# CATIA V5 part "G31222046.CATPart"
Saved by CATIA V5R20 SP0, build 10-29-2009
Part number: G31222046
Revision: 5
Definition: design
Nomenclature: G31222046
Source: made
Description: NOT SPECIFIED
Bounding box of the stored display mesh (mm): x -8 to 46, y -17.322 to 17.322, z -17.5 to 17.5
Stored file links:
  C:\Users\Raffaele\Desktop\3D X SITO CF\BOLEX\23-BUSH REF 312\G31222046.CATPart

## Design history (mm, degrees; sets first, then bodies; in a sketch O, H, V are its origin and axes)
Body1 "MANIFOLD_SOLID_BREP #10463" (main body)
  Solid1: solid without history
Body2 "MANIFOLD_SOLID_BREP #10614"
  Solid2: solid without history
Body3 "MANIFOLD_SOLID_BREP #10765"
  Solid3: solid without history
Body4 "MANIFOLD_SOLID_BREP #10916"
  Solid4: solid without history
Body5 "MANIFOLD_SOLID_BREP #11067"
  Solid5: solid without history
Body6 "MANIFOLD_SOLID_BREP #11216"
  Solid6: solid without history
Body7 "MANIFOLD_SOLID_BREP #11365"
  Solid7: solid without history
Body8 "MANIFOLD_SOLID_BREP #11514"
  Solid8: solid without history
Body9 "MANIFOLD_SOLID_BREP #11663"
  Solid9: solid without history
Body10 "MANIFOLD_SOLID_BREP #11812"
  Solid10: solid without history
Body11 "MANIFOLD_SOLID_BREP #11961"
  Solid11: solid without history
Body12 "MANIFOLD_SOLID_BREP #12110"
  Solid12: solid without history
Body13 "MANIFOLD_SOLID_BREP #12259"
  Solid13: solid without history
Body14 "MANIFOLD_SOLID_BREP #12408"
  Solid14: solid without history
Body15 "MANIFOLD_SOLID_BREP #12557"
  Solid15: solid without history
Body16 "MANIFOLD_SOLID_BREP #12706"
  Solid16: solid without history
Body17 "MANIFOLD_SOLID_BREP #12855"
  Solid17: solid without history
Body18 "MANIFOLD_SOLID_BREP #13004"
  Solid18: solid without history
Body19 "MANIFOLD_SOLID_BREP #13153"
  Solid19: solid without history
Body20 "MANIFOLD_SOLID_BREP #13302"
  Solid20: solid without history
Body21 "MANIFOLD_SOLID_BREP #13451"
  Solid21: solid without history
Body22 "MANIFOLD_SOLID_BREP #13600"
  Solid22: solid without history
Body23 "MANIFOLD_SOLID_BREP #13749"
  Solid23: solid without history
Body24 "MANIFOLD_SOLID_BREP #13898"
  Solid24: solid without history
Body25 "MANIFOLD_SOLID_BREP #14047"
  Solid25: solid without history
Body26 "MANIFOLD_SOLID_BREP #14196"
  Solid26: solid without history
Body27 "MANIFOLD_SOLID_BREP #14345"
  Solid27: solid without history
Body28 "MANIFOLD_SOLID_BREP #14494"
  Solid28: solid without history
Body29 "MANIFOLD_SOLID_BREP #14643"
  Solid29: solid without history
Body30 "MANIFOLD_SOLID_BREP #14792"
  Solid30: solid without history
Body31 "MANIFOLD_SOLID_BREP #14941"
  Solid31: solid without history
Body32 "MANIFOLD_SOLID_BREP #15092"
  Solid32: solid without history
Body33 "MANIFOLD_SOLID_BREP #15243"
  Solid33: solid without history
Body34 "MANIFOLD_SOLID_BREP #15392"
  Solid34: solid without history
Body35 "MANIFOLD_SOLID_BREP #15541"
  Solid35: solid without history
Body36 "MANIFOLD_SOLID_BREP #15690"
  Solid36: solid without history
Body37 "MANIFOLD_SOLID_BREP #15839"
  Solid37: solid without history
Body38 "MANIFOLD_SOLID_BREP #15988"
  Solid38: solid without history
Body39 "MANIFOLD_SOLID_BREP #16137"
  Solid39: solid without history
Body40 "MANIFOLD_SOLID_BREP #16286"
  Solid40: solid without history
Body41 "MANIFOLD_SOLID_BREP #16435"
  Solid41: solid without history
Body42 "MANIFOLD_SOLID_BREP #16584"
  Solid42: solid without history
Body43 "MANIFOLD_SOLID_BREP #16733"
  Solid43: solid without history
Body44 "MANIFOLD_SOLID_BREP #16882"
  Solid44: solid without history
Body45 "MANIFOLD_SOLID_BREP #17031"
  Solid45: solid without history
Body46 "MANIFOLD_SOLID_BREP #17180"
  Solid46: solid without history
Body47 "MANIFOLD_SOLID_BREP #17329"
  Solid47: solid without history
Body48 "MANIFOLD_SOLID_BREP #17480"
  Solid48: solid without history
Body49 "MANIFOLD_SOLID_BREP #17631"
  Solid49: solid without history
Body50 "MANIFOLD_SOLID_BREP #17780"
  Solid50: solid without history
Body51 "MANIFOLD_SOLID_BREP #17929"
  Solid51: solid without history
Body52 "MANIFOLD_SOLID_BREP #18078"
  Solid52: solid without history
Body53 "MANIFOLD_SOLID_BREP #18227"
  Solid53: solid without history
Body54 "MANIFOLD_SOLID_BREP #18376"
  Solid54: solid without history
Body55 "MANIFOLD_SOLID_BREP #18525"
  Solid55: solid without history
Body56 "MANIFOLD_SOLID_BREP #18674"
  Solid56: solid without history
Body57 "MANIFOLD_SOLID_BREP #18823"
  Solid57: solid without history
Body58 "MANIFOLD_SOLID_BREP #18972"
  Solid58: solid without history
Body59 "MANIFOLD_SOLID_BREP #19121"
  Solid59: solid without history
Body60 "MANIFOLD_SOLID_BREP #19270"
  Solid60: solid without history
Body61 "MANIFOLD_SOLID_BREP #19419"
  Solid61: solid without history
Body62 "MANIFOLD_SOLID_BREP #19568"
  Solid62: solid without history
Body63 "MANIFOLD_SOLID_BREP #19717"
  Solid63: solid without history
Body64 "MANIFOLD_SOLID_BREP #19868"
  Solid64: solid without history
Body65 "MANIFOLD_SOLID_BREP #20019"
  Solid65: solid without history
Body66 "MANIFOLD_SOLID_BREP #20168"
  Solid66: solid without history
Body67 "MANIFOLD_SOLID_BREP #20317"
  Solid67: solid without history
Body68 "MANIFOLD_SOLID_BREP #20466"
  Solid68: solid without history
Body69 "MANIFOLD_SOLID_BREP #20615"
  Solid69: solid without history
Body70 "MANIFOLD_SOLID_BREP #20764"
  Solid70: solid without history
Body71 "MANIFOLD_SOLID_BREP #20913"
  Solid71: solid without history
Body72 "MANIFOLD_SOLID_BREP #21062"
  Solid72: solid without history
Body73 "MANIFOLD_SOLID_BREP #21211"
  Solid73: solid without history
